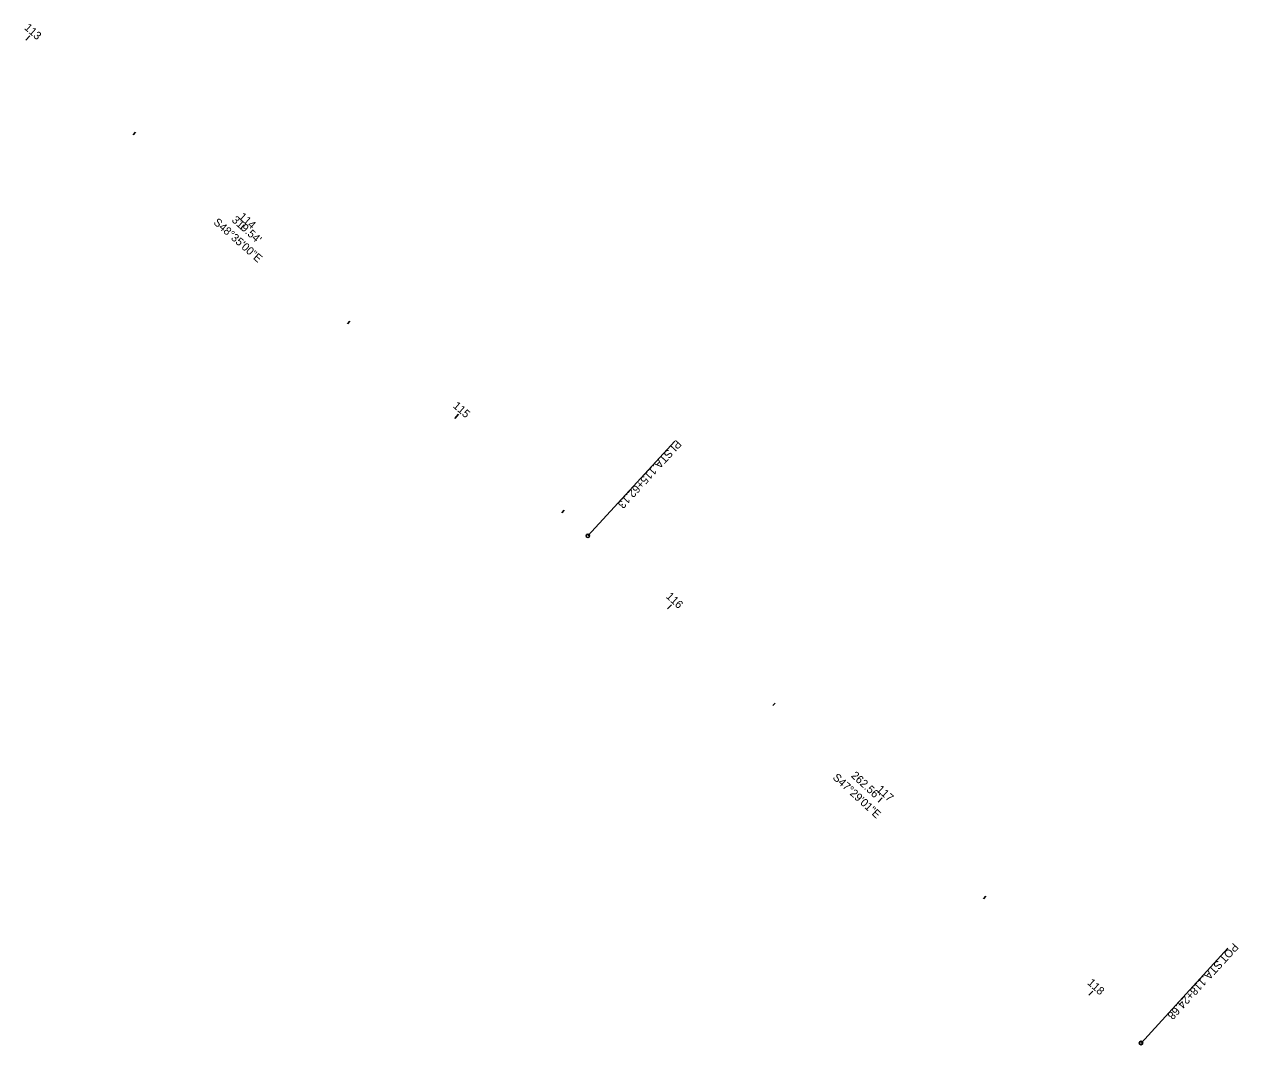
# Model space of a CAD drawing. Extents: x 1600023 to 1602131, y 285824 to 287284.
# Drawn here: x 1601706.5 to 1602131.3, y 285824.1 to 286181.1 of the extents above; entities that cross this region are included whole.
import ezdxf

# ---------------------------------------------------------------- set-up
doc = ezdxf.new("R2010")
doc.units = 0
for name, color, linetype in [('GE_P_Alignment_100_Bearings', 7, 'Continuous'), ('GE_P_Alignment_100_Cardinal_Points', 7, 'Continuous'), ('GE_P_Alignment_100_Distances', 7, 'Continuous'), ('GE_P_Alignment_100_Stations', 7, 'Continuous')]:
    doc.layers.add(name, color=color, linetype=linetype)

msp = doc.modelspace()

# ---------------------------------------------------------------- linework, layer by layer
at = {"layer": 'GE_P_Alignment_100_Cardinal_Points'}
for p, q in [((1601903.64, 286002.16), (1601934.05, 286035.33)), ((1602097.17, 285824.72), (1602127.58, 285857.89))]:
    msp.add_line(p, q, dxfattribs=at)
for centre in [(1601903.64, 286002.16), (1602097.17, 285824.72)]:
    msp.add_circle(centre, 0.6, dxfattribs=at)
at = {"layer": 'GE_P_Alignment_100_Stations'}
for p, q in [((1601707.07, 286175.57), (1601708.39, 286177.06)), ((1601744.56, 286142.49), (1601745.36, 286143.39)), ((1601782.06, 286109.41), (1601783.38, 286110.91)), ((1601819.55, 286076.34), (1601820.35, 286077.24)), ((1601857.05, 286043.26), (1601858.37, 286044.76)), ((1601894.55, 286010.18), (1601895.34, 286011.08)), ((1601931.56, 285976.57), (1601932.91, 285978.04)), ((1601968.41, 285942.78), (1601969.22, 285943.66)), ((1602005.26, 285908.99), (1602006.62, 285910.46)), ((1602042.12, 285875.2), (1602042.93, 285876.08)), ((1602078.97, 285841.41), (1602080.32, 285842.88))]:
    msp.add_line(p, q, dxfattribs=at)

# ---------------------------------------------------------------- texts
at = {"layer": 'GE_P_Alignment_100_Bearings'}
for s, rotation, p in [('S48°35\'00"E', 318.5834, (1601772.45, 286111.49)), ('S47°29\'01"E', 317.4836, (1601989.1, 285917.3))]:
    msp.add_text(s, height=2.8, rotation=rotation, dxfattribs=at).set_placement(p)
at = {"layer": 'GE_P_Alignment_100_Cardinal_Points'}
for s, p in [('PI', (1601934.64, 286035.91)), (' STA. ', (1601932.34, 286033.41)), ('115+62.13', (1601925.96, 286026.44)), ('POT', (1602129.49, 285859.92)), (' STA. ', (1602124.63, 285854.61)), ('118+24.68', (1602118.24, 285847.64))]:
    msp.add_text(s, height=2.8, rotation=227.4836, dxfattribs=at).set_placement(p)
at = {"layer": 'GE_P_Alignment_100_Distances'}
for s, rotation, p in [("319.54'", 318.5834, (1601778.84, 286112.3)), ("262.56'", 317.4836, (1601995.51, 285917.99))]:
    msp.add_text(s, height=2.8, rotation=rotation, dxfattribs=at).set_placement(p)
at = {"layer": 'GE_P_Alignment_100_Stations'}
for s, rotation, p in [('113', 318.5834, (1601706.27, 286179.6)), ('114', 318.5834, (1601781.26, 286113.45)), ('115', 318.5834, (1601856.23, 286047.32)), ('116', 317.4836, (1601930.77, 285980.68)), ('117', 317.4836, (1602004.44, 285913.14)), ('118', 317.4836, (1602078.2, 285845.5))]:
    msp.add_text(s, height=2.8, rotation=rotation, dxfattribs=at).set_placement(p)

doc.saveas('drawing.dxf')
